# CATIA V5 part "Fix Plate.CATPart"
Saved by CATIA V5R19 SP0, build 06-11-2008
Part number: Fix Plate
Bounding box of the stored display mesh (mm): x -45 to 45, y -150 to 150, z -40 to 230
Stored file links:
  D:\Shriniwas\v5_r19\c16_CAT_v5r19\c16_Part\Slide curve Joint\Tut_5\Fix Plate.CATPart
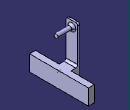
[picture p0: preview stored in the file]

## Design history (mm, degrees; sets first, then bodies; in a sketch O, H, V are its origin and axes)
Body1 (main body)
  Sketch1 on yz-plane, origin (0, 0, 0), H (0, 1, 0), V (0, 0, 1)
    line L1 (150, 40) -> (150, -40)
    line L2 (150, -40) -> (-150, -40)
    line L3 (-150, -40) -> (-150, 40)
    line L4 (-150, 40) -> (150, 40)
    length L4 = 300
    length L1 = 80
    vertical: L1 V, L3 V
    horizontal: L2 H, L4 H
    equidistance: L1 L3 O, L2 L4 O
  Pad1: profile Sketch1, direction (1, 0, 0), length 30
  Point1: type OnCurve, Support edge [face of Pad1 from Sketch1.L4 | end face of Pad1], Ratio 0.5
  Sketch2 on start face of Pad1, origin (0, 0, 0), H (0, -1, 0), V (0, 0, 1)
    circle A1 centre (0, 200) radius 10
    point P1 (0, 200)
    reference projected line E1 (-150, 40) -> (150, 40) from edge [start face of Pad1 | face of Pad1 from Sketch1.L4]
    radius A1 = 10
    distance E1 P1 = 160
    coincidence: P1 V
  Pad2: profile Sketch2, direction (1, 0, 0), length 45, mirrored extent
  Sketch3 on start face of Pad2, origin (-45, 0, 0), H (0, -1, 0), V (0, 0, 1)
    line L1 (30, -40) -> (-30, -40)
    line L2 (-30, -40) -> (-30, 230)
    line L3 (-30, 230) -> (30, 230)
    line L4 (30, 230) -> (30, -40)
    reference projected line E1 (-150, 40) -> (150, 40) from edge [start face of Pad1 | face of Pad1 from Sketch1.L4]
    length L3 = 60
    distance V L2 = 30
    distance E1 L3 = 190
    horizontal: L1 H, L3 H
    vertical: L2 V, L4 V
  Pad3: profile Sketch3, direction (1, 0, 0), length 10
  Sketch4 on end face of Pad3, origin (-35, 0, 0), H (0, 1, 0), V (0, 0, 1)
    line L1 (-30, 40) -> (30, 40)
    line L2 (30, 40) -> (30, -40)
    line L3 (30, -40) -> (-30, -40)
    line L4 (-30, -40) -> (-30, 40)
    reference projected line E1 (150, 40) -> (-150, 40) from edge [face of Pad1 from Sketch1.L4 | end face of Pad1]
    reference projected line E2 (-30, -40) -> (-30, 230) from edge [end face of Pad3 | face of Pad3 from Sketch3.L4]
    reference projected line E3 (-150, -40) -> (150, -40) from edge [face of Pad1 from Sketch1.L2 | end face of Pad1]
    reference projected line E4 (30, 230) -> (30, -40) from edge [end face of Pad3 | face of Pad3 from Sketch3.L2]
    horizontal: L1 H, L3 H
    vertical: L2 V, L4 V
    coincidence: L1 E1, L4 E2, L3 E3, L2 E4
  Pad4: profile Sketch4, direction (1, 0, 0), up to the existing solid (limit type 2)
  Fillet1: radius 10, on edge [face of Pad3 from Sketch3.L3 | face of Pad3]; edge [face of Pad2 from Sketch2.A1 | end face of Pad3]; edge [face of Pad4 | face of Pad3 from Sketch3.L3]; edge [end face of Pad3 | face of Pad1]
